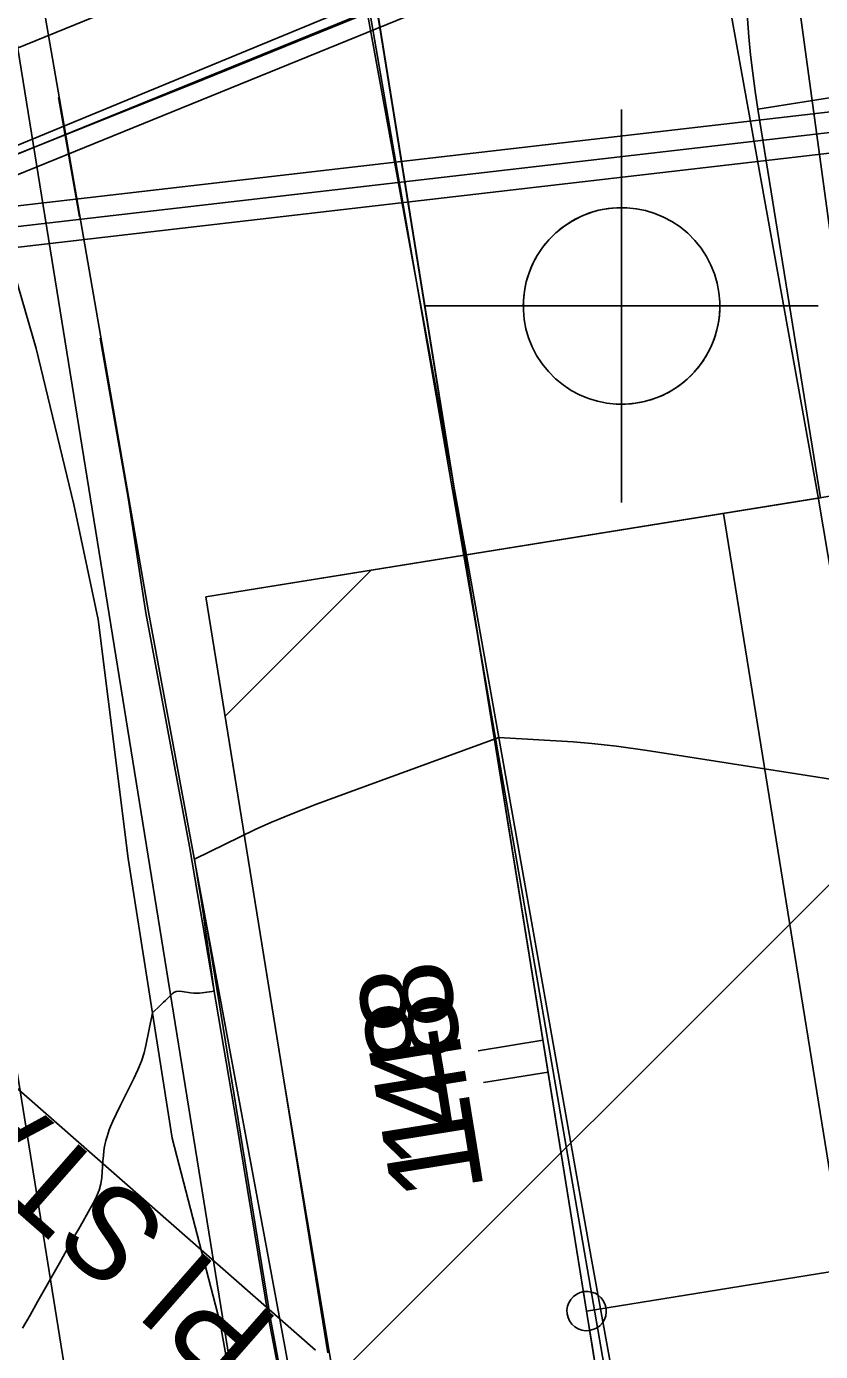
# Model space of a CAD drawing. Extents: x 2030588 to 2035216, y 462285 to 465007.
# Drawn here: x 2031240.32 to 2031264.56, y 464273.04 to 464313.48 of the extents above; entities that cross this region are included whole.
import ezdxf

# ---------------------------------------------------------------- set-up
doc = ezdxf.new("R2010")
doc.units = 0
for name, color, linetype in [('Default', 7, 'Continuous'), ('DR_P_Culvert', 7, 'Continuous'), ('DR_X_Cells', 7, 'Continuous'), ('DR_X_Culvert', 7, 'Continuous'), ('DR_X_Storm_Sewer', 7, 'Continuous'), ('DT_P_Pavement_Surface', 7, 'Continuous'), ('DT_X_Contour_Minor', 7, 'Continuous'), ('DV_X_Property_Line', 7, 'Continuous'), ('GE_P_Alignment', 7, 'Continuous'), ('GE_P_Alignment_100_Cardinal_Points', 7, 'Continuous'), ('GE_X_Alignment', 7, 'Continuous'), ('GE_X_Alignment_100_Cardinal_Points', 7, 'Continuous'), ('GE_X_Alignment_100_Stations', 7, 'Continuous'), ('GT_Project_Soil_Boring', 7, 'Continuous'), ('MT_P_Temp_Road', 7, 'Continuous'), ('PV_P_EOP', 7, 'Continuous'), ('PV_P_Shoulder', 7, 'Continuous'), ('PV_X_COP', 7, 'Continuous'), ('PV_X_EOP', 7, 'Continuous'), ('PV_X_Shoulder_Aggregate', 7, 'Continuous'), ('RW_X_CL', 7, 'Continuous'), ('RW_X_CL_100_Stations', 7, 'Continuous'), ('SC_Scratch1', 7, 'Continuous'), ('SV_X_Break_Lines', 7, 'Continuous')]:
    doc.layers.add(name, color=color, linetype=linetype)

msp = doc.modelspace()

# ---------------------------------------------------------------- linework, layer by layer
at = {"layer": 'Default'}
msp.add_line((2031245.351, 464311.713), (2031245.351, 464311.713), dxfattribs=at)
at = {"layer": 'DR_P_Culvert'}
for p, q in [((2031291.465, 464330.528), (2031223.863, 464302.998)), ((2031291.685, 464329.988), (2031224.083, 464302.457))]:
    msp.add_line(p, q, dxfattribs=at)
at = {"layer": 'DR_X_Cells'}
for points in [[(2031268.463, 464311.299), (2031228.624, 464306.683), (2031220.262, 464304.833)], [(2031268.607, 464310.058), (2031228.832, 464305.449), (2031220.532, 464303.612)]]:
    msp.add_lwpolyline(points, dxfattribs=at)
at = {"layer": 'DR_X_Culvert'}
msp.add_line((2031221.368, 464302.132), (2031288.089, 464329.716), dxfattribs=at)
at = {"layer": 'DR_X_Storm_Sewer'}
for points in [[(2031285.803, 464335.154), (2031284.43, 464334.622), (2031260.346, 464324.908), (2031242.932, 464317.706), (2031218.984, 464307.814), (2031221.368, 464302.132), (2031245.351, 464311.713), (2031262.878, 464318.835), (2031286.679, 464329.115), (2031288.089, 464329.716)], [(2031220.397, 464304.222), (2031228.728, 464306.066), (2031268.535, 464310.679)]]:
    msp.add_lwpolyline(points, dxfattribs=at)
at = {"layer": 'DT_P_Pavement_Surface'}
for p, q in [((2031246.387, 464292.429), (2031250.846, 464296.887)), ((2031249.704, 464272.177), (2031269.72, 464292.193))]:
    msp.add_line(p, q, dxfattribs=at)
msp.add_lwpolyline([(2031257.072, 464231.726), (2031252.323, 464256.477), (2031248.187, 464281.266), (2031245.799, 464296.073), (2031268.504, 464299.734), (2031270.891, 464284.927), (2031274.963, 464260.519), (2031278.406, 464242.26), (2031279.291, 464236.286)], dxfattribs=at)
at = {"layer": 'DT_X_Contour_Minor'}
msp.add_lwpolyline([(2031265.965, 464290.332), (2031260.371, 464291.215), (2031259.261, 464291.384), (2031258.33, 464291.513), (2031257.577, 464291.602), (2031257.002, 464291.65), (2031254.737, 464291.78), (2031250.093, 464290.086), (2031249.173, 464289.744), (2031248.401, 464289.444), (2031247.779, 464289.186), (2031247.306, 464288.971), (2031245.448, 464288.063), (2031245.595, 464287.185), (2031245.63, 464286.969), (2031245.672, 464286.695), (2031245.72, 464286.365), (2031245.776, 464285.978), (2031246.051, 464284.038), (2031245.684, 464283.985), (2031245.603, 464283.977), (2031245.517, 464283.976), (2031245.426, 464283.981), (2031245.331, 464283.993), (2031245.07, 464284.033), (2031244.977, 464284.039), (2031244.895, 464284.028), (2031244.824, 464283.999), (2031244.763, 464283.953), (2031244.616, 464283.807), (2031244.562, 464283.753), (2031244.508, 464283.7), (2031244.456, 464283.65), (2031244.405, 464283.602), (2031244.168, 464283.379), (2031243.968, 464282.378), (2031243.912, 464282.153), (2031243.83, 464281.907), (2031243.722, 464281.64), (2031243.587, 464281.352), (2031243.193, 464280.557), (2031243.061, 464280.286), (2031242.96, 464280.071), (2031242.889, 464279.912), (2031242.849, 464279.809), (2031242.785, 464279.608), (2031242.762, 464279.538), (2031242.744, 464279.478), (2031242.73, 464279.429), (2031242.72, 464279.39), (2031242.699, 464279.299), (2031242.69, 464279.246), (2031242.68, 464279.154), (2031242.669, 464279.023), (2031242.656, 464278.854), (2031242.62, 464278.35), (2031242.594, 464278.159), (2031242.541, 464277.965), (2031242.463, 464277.767), (2031242.359, 464277.565), (2031242.048, 464277.022), (2031241.915, 464276.789), (2031241.75, 464276.498), (2031241.553, 464276.149), (2031241.325, 464275.741), (2031240.673, 464274.578), (2031240.431, 464274.155), (2031240.196, 464273.757)], dxfattribs=at)
at = {"layer": 'DV_X_Property_Line'}
msp.add_line((2031240.355, 464374.314), (2031264.413, 464235.242), dxfattribs=at)
at = {"layer": 'GE_P_Alignment'}
msp.add_line((2031292.185, 464334.061), (2031215.324, 464302.759), dxfattribs=at)
at = {"layer": 'GE_P_Alignment_100_Cardinal_Points'}
msp.add_line((2031215.324, 464302.759), (2031249.142, 464273.079), dxfattribs=at)
at = {"layer": 'GE_X_Alignment'}
msp.add_line((2031257.417, 464274.275), (2031203.458, 464608.932), dxfattribs=at)
msp.add_ellipse((2032214.825, 464428.293), major_axis=(-647.882, 721.538), ratio=0.999987, start_param=0.998641, end_param=1.129131, dxfattribs=at)
at = {"layer": 'GE_X_Alignment_100_Cardinal_Points'}
msp.add_line((2031257.417, 464274.275), (2031301.838, 464281.437), dxfattribs=at)
msp.add_ellipse((2031257.417, 464274.275), major_axis=(-0.4, 0.447), ratio=0.999987, dxfattribs=at)
at = {"layer": 'GE_X_Alignment_100_Stations'}
msp.add_line((2031256.084, 464282.539), (2031254.11, 464282.221), dxfattribs=at)
at = {"layer": 'GT_Project_Soil_Boring'}
for p, q in [((2031258.484, 464304.953), (2031258.484, 464310.953)), ((2031258.484, 464307.953), (2031258.484, 464304.953)), ((2031258.484, 464304.953), (2031252.484, 464304.953)), ((2031258.484, 464304.953), (2031255.484, 464304.953)), ((2031258.484, 464304.953), (2031258.484, 464298.954)), ((2031258.484, 464304.953), (2031264.483, 464304.953)), ((2031258.484, 464301.954), (2031258.484, 464304.953)), ((2031258.484, 464304.953), (2031261.484, 464304.953))]:
    msp.add_line(p, q, dxfattribs=at)
msp.add_ellipse((2031258.484, 464304.953), major_axis=(-2.002, 2.234), ratio=0.999987, dxfattribs=at)
for start_param, end_param in [(5.552948, 7.123745), (2.411249, 3.982045)]:
    msp.add_ellipse((2031258.484, 464304.953), major_axis=(-2.001, 2.235), ratio=0.999987, start_param=start_param, end_param=end_param, dxfattribs=at)
at = {"layer": 'MT_P_Temp_Road'}
msp.add_lwpolyline([(2031261.594, 464298.62), (2031265.314, 464275.547), (2031265.314, 464275.546)], dxfattribs=at)
at = {"layer": 'PV_P_EOP'}
for p, q in [((2031221.032, 464430.836), (2031246.558, 464272.527)), ((2031293.243, 464315.898), (2031262.643, 464310.954)), ((2031262.643, 464310.954), (2031264.555, 464299.097)), ((2031245.799, 464296.073), (2031264.555, 464299.097)), ((2031245.799, 464296.073), (2031249.519, 464273.004))]:
    msp.add_line(p, q, dxfattribs=at)
msp.add_ellipse((2031293.243, 464315.898), major_axis=(-20.684, 23.086), ratio=0.999987, start_param=6.157653, end_param=7.283599, dxfattribs=at)
at = {"layer": 'PV_P_Shoulder'}
msp.add_line((2031241.622, 464271.732), (2031237.902, 464294.8), dxfattribs=at)
msp.add_ellipse((2031293.928, 464317.64), major_axis=(-18.684, 20.851), ratio=0.999987, start_param=6.213097, end_param=7.341063, dxfattribs=at)
at = {"layer": 'PV_X_COP'}
msp.add_lwpolyline([(2031345.188, 464029.832), (2031333.67, 464047.134), (2031321.647, 464066.894), (2031312.766, 464083.536), (2031304.429, 464100.871), (2031297.296, 464118.161), (2031290.962, 464134.785), (2031285.598, 464151.007), (2031280.258, 464168.89), (2031275.568, 464187.058), (2031270.599, 464208.238), (2031269.533, 464213.253), (2031265.078, 464235.308), (2031261.071, 464256.548), (2031257.559, 464275.914), (2031253.749, 464297.335), (2031250.237, 464316.556), (2031248.155, 464328.465)], dxfattribs=at)
at = {"layer": 'PV_X_EOP'}
for points in [[(2031295.06, 464096.69), (2031287.81, 464114.209), (2031281.552, 464131.387), (2031276.172, 464147.96), (2031272.883, 464159.049), (2031270.831, 464166.359), (2031266.261, 464184.745), (2031263.597, 464196.521), (2031261.604, 464205.334), (2031260.218, 464211.323), (2031255.622, 464233.278), (2031251.626, 464254.611), (2031248.06, 464273.969), (2031245.809, 464286.12), (2031244.042, 464295.612), (2031240.727, 464314.748), (2031237.529, 464334.128), (2031234.115, 464352.392), (2031233.443, 464356.077), (2031230.628, 464372.695), (2031227.228, 464392.461), (2031223.822, 464412.655), (2031220.382, 464434.076), (2031216.941, 464456.075)], [(2031353.162, 464035.71), (2031341.874, 464052.676), (2031332.716, 464067.744), (2031330.521, 464071.931), (2031322.023, 464088.196), (2031314.108, 464105.099), (2031307.351, 464122.147), (2031301.267, 464138.466), (2031296.143, 464154.308), (2031290.945, 464171.988), (2031286.324, 464189.894), (2031281.443, 464210.564), (2031280.322, 464215.544), (2031275.666, 464237.435), (2031271.643, 464258.648), (2031268.07, 464277.87), (2031264.482, 464299.113), (2031261, 464318.439), (2031259.92, 464324.373)]]:
    msp.add_lwpolyline(points, dxfattribs=at)
at = {"layer": 'PV_X_Shoulder_Aggregate'}
for points in [[(2031255.511, 464233.314), (2031251.402, 464254.597), (2031247.773, 464274.033), (2031245.809, 464286.12), (2031244.042, 464295.612), (2031240.727, 464314.748), (2031237.529, 464334.128), (2031234.115, 464352.392), (2031233.443, 464356.077), (2031232.17, 464359.083), (2031229.545, 464365.856), (2031227.503, 464372.246), (2031224.664, 464382.428), (2031222.926, 464391.795), (2031219.919, 464412.021), (2031218.49, 464422.889), (2031218.4, 464433.793), (2031218.362, 464445.956)], [(2031277.635, 464237.84), (2031273.355, 464258.914), (2031270.066, 464278.166), (2031265.916, 464299.362), (2031263.298, 464318.606), (2031263.318, 464322.998), (2031263.199, 464325.189), (2031262.878, 464328.279), (2031260.848, 464338.194), (2031257.913, 464356.817), (2031254.754, 464370.404), (2031253.155, 464376.691), (2031250.944, 464380.086), (2031250.391, 464381.285), (2031248.022, 464396.129), (2031244.492, 464415.82), (2031241.204, 464437.394)]]:
    msp.add_lwpolyline(points, dxfattribs=at)
at = {"layer": 'RW_X_CL'}
msp.add_line((2031264.454, 464230.531), (2031192.714, 464676.453), dxfattribs=at)
at = {"layer": 'RW_X_CL_100_Stations'}
msp.add_line((2031256.243, 464281.57), (2031254.269, 464281.252), dxfattribs=at)
at = {"layer": 'SC_Scratch1'}
for p, q in [((2031253.697, 464297.347), (2031247.33, 464336.833)), ((2031215.324, 464302.759), (2031250.513, 464317.09))]:
    msp.add_line(p, q, dxfattribs=at)
at = {"layer": 'SV_X_Break_Lines'}
msp.add_line((2031241.303, 464311.311), (2031241.944, 464307.67), dxfattribs=at)
for points in [[(2031234.299, 464339.736), (2031235.831, 464334.012), (2031237.674, 464325.096), (2031237.79, 464321.855), (2031238.236, 464314.044), (2031239.54, 464307.38), (2031240.618, 464303.654), (2031241.764, 464298.897), (2031242.506, 464295.382), (2031243.425, 464288.087), (2031244.772, 464279.554), (2031246.229, 464273.905), (2031248.388, 464261.823), (2031249.64, 464254.225), (2031251.703, 464242.927), (2031253.829, 464232.975)], [(2031242.571, 464303.969), (2031243.425, 464299.098), (2031243.969, 464295.585), (2031245.298, 464288.452), (2031246.745, 464279.965), (2031247.716, 464274.02), (2031249.983, 464262.131), (2031251.376, 464254.593), (2031253.574, 464243.217), (2031255.463, 464233.437), (2031257.382, 464223.97)]]:
    msp.add_lwpolyline(points, dxfattribs=at)

# ---------------------------------------------------------------- texts
at = {"layer": 'GE_P_Alignment_100_Cardinal_Points'}
for s, p in [(' STA. ', (2031245.558, 464276.168)), ('PI', (2031248.107, 464273.931))]:
    msp.add_text(s, height=2.7997, rotation=138.729, dxfattribs=at).set_placement(p)
at = {"layer": 'GE_X_Alignment_100_Stations'}
msp.add_text('148', height=2.7997, rotation=99.1593, dxfattribs=at).set_placement((2031254.133, 464278.934))
at = {"layer": 'RW_X_CL_100_Stations'}
msp.add_text('148', height=2.7997, rotation=99.1395, dxfattribs=at).set_placement((2031254.291, 464277.965))

doc.saveas('drawing.dxf')
